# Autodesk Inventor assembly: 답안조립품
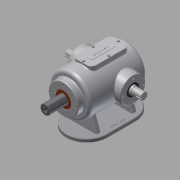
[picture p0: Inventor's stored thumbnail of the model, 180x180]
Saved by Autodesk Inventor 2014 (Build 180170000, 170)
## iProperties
Created: 2016-08
Part Number: 답안조립품
Document SubType Name: Assembly
Designer: SCD-A13
Mass: 7983.41 g
Surface Area: 4315.56 cm^2
Volume: 1877.98 cm^3
Density: 4.25107 g/cm^3
Author: SCD-A13
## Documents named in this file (16)
- C:\Users\SCD-A13\Desktop\360808V1010\답안조립품.iam
- C:\Users\SCD-A13\Desktop\360808V1010\본체.ipt
- C:\Users\SCD-A13\Desktop\360808V1010\플레이트.ipt
- C:\Users\SCD-A13\Desktop\360808V1010\베어링 6205.ipt
- 베어링 6205.ipt
- C:\Users\SCD-A13\Desktop\360808V1010\축 커버.ipt
- C:\Users\SCD-A13\Desktop\360808V1010\오일실.ipt
- 오일실.ipt
- C:\Users\SCD-A13\Desktop\360808V1010\슬라이드 커버.ipt
- C:\Users\SCD-A13\Desktop\360808V1010\부시.ipt
- C:\Users\SCD-A13\Desktop\360808V1010\슬라이드.ipt
- C:\Users\SCD-A13\Desktop\360808V1010\편심축.ipt
- C:\Users\SCD-A13\Desktop\360808V1010\상부커버.ipt
- C:\Users\SCD-A13\Desktop\360808V1010\육각머리볼트 M4.ipt
- C:\Users\SCD-A13\Desktop\360808V1010\볼트 M4x0.7.ipt
- C:\Users\SCD-A13\Desktop\360808V1010\가변스프링.ipt
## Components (14 placed, 3 different names)
1. 플레이트:1
2. 가변스프링:1
3. M4x0.7:3
4. M4x0.7:4
5. M4x0.7:5
6. M4x0.7:6
7. M4x0.7:2
8. M4x0.7:7
9. M4x0.7:8
10. M4x0.7:9
11. M4x0.7:1
12. M4x0.7:10
13. M4x0.7:11
14. M4x0.7:12
